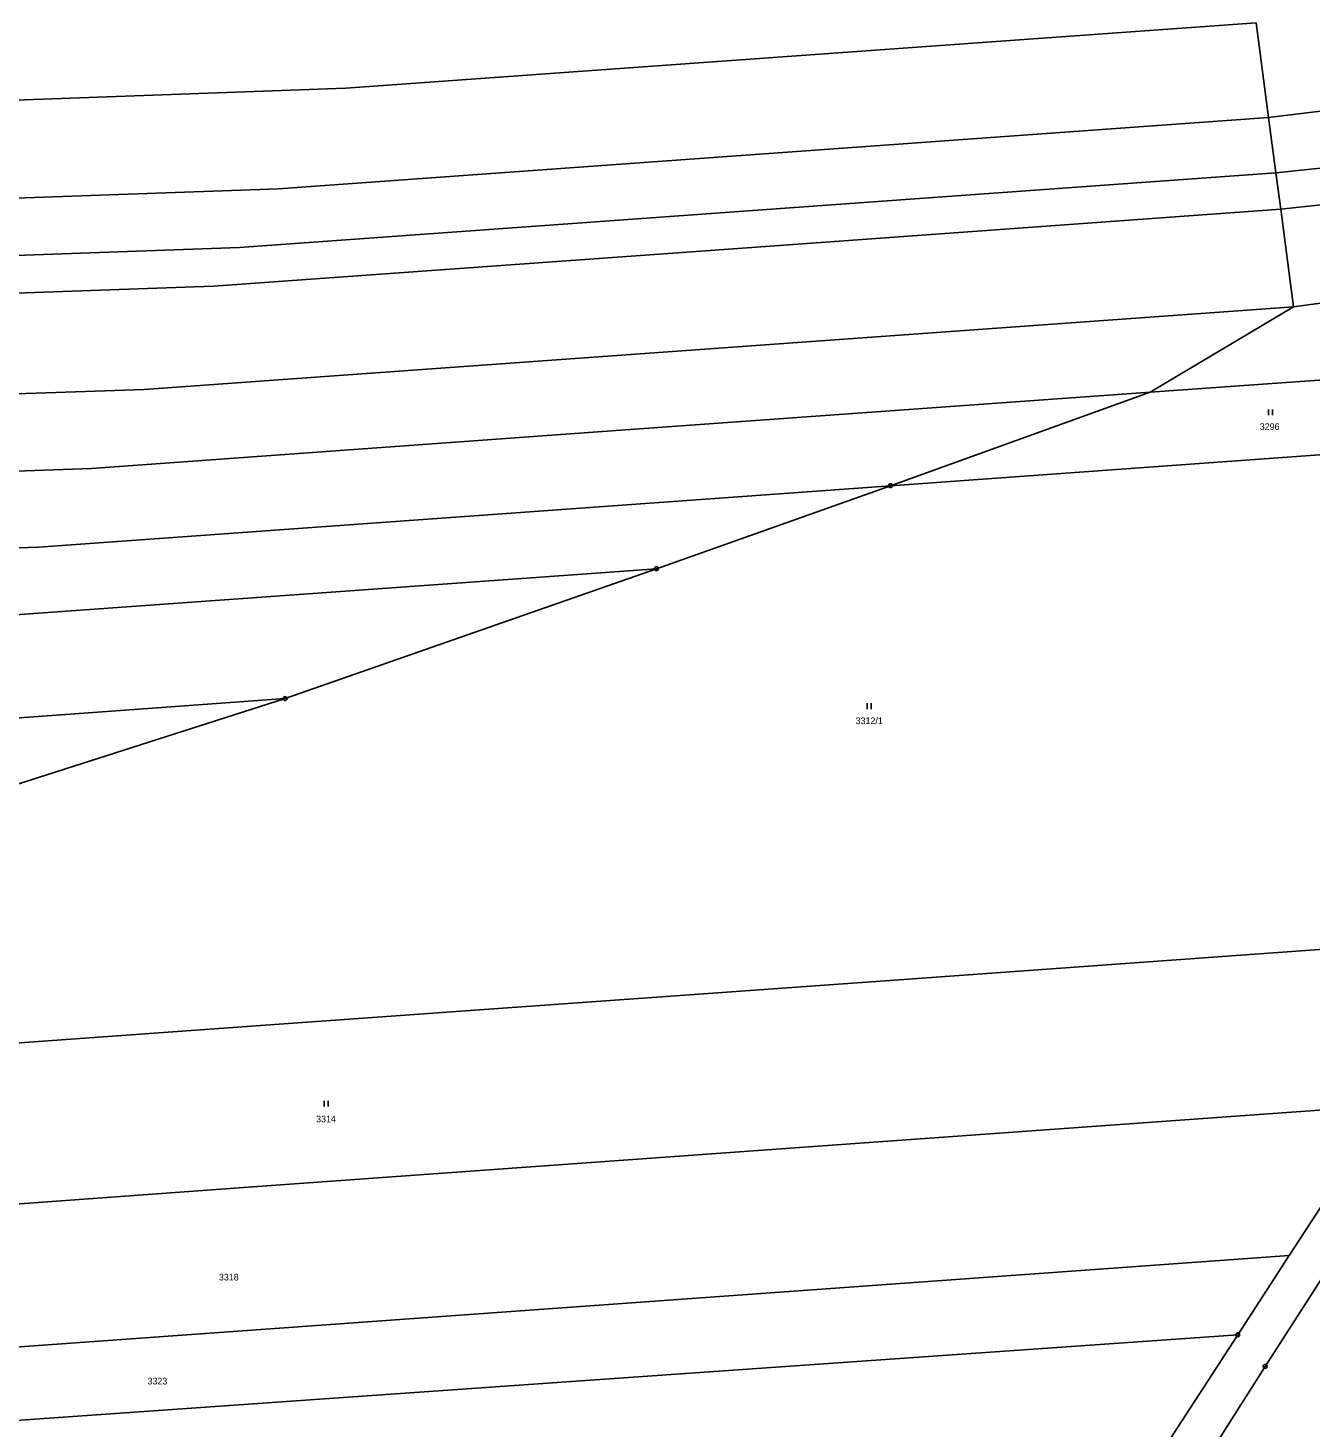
# Model space of a CAD drawing. Extents: x -618848 to -615803, y -1044450 to -1042254.
# Drawn here: x -617311.9 to -616984, y -1043703.1 to -1043345.1 of the extents above; entities that cross this region are included whole.
import ezdxf
from ezdxf.enums import TextEntityAlignment as Align

# ---------------------------------------------------------------- set-up
doc = ezdxf.new("R2010")
doc.units = 0
doc.header["$LTSCALE"] = 0.68
for name, color, linetype, lineweight in [('1', 7, 'Continuous', 25), ('3', 7, 'Continuous', 25), ('8', 7, 'Continuous', 25)]:
    doc.layers.add(name, color=color, linetype=linetype, lineweight=lineweight)
doc.layers.add('2', color=7, linetype='Continuous')

msp = doc.modelspace()

# ---------------------------------------------------------------- linework, layer by layer
at = {"layer": '1'}
for p, q in [((-617114.36, -1043352.18), (-616998.06, -1043343.8)), ((-616998.06, -1043343.8), (-616994.86, -1043368.03)), ((-617230.67, -1043360.55), (-617114.36, -1043352.18)), ((-617360.78, -1043365.17), (-617230.67, -1043360.55)), ((-616994.86, -1043368.03), (-616925.06, -1043359.49)), ((-616994.86, -1043368.03), (-617121.36, -1043377.14)), ((-616994.86, -1043368.03), (-616993, -1043382.17)), ((-616993, -1043382.17), (-616927.39, -1043375.26)), ((-617121.36, -1043377.14), (-617247.87, -1043386.25)), ((-617125.46, -1043391.7), (-616993, -1043382.17)), ((-616993, -1043382.17), (-616991.77, -1043391.49)), ((-617247.87, -1043386.25), (-617368.94, -1043390.54)), ((-616991.77, -1043391.49), (-616929.96, -1043384.84)), ((-617257.91, -1043401.24), (-617125.46, -1043391.7)), ((-616991.77, -1043391.49), (-617128.15, -1043401.31)), ((-616991.77, -1043391.49), (-616988.49, -1043416.39)), ((-617387.08, -1043405.83), (-617257.91, -1043401.24)), ((-617128.15, -1043401.31), (-617264.53, -1043411.13)), ((-617264.53, -1043411.13), (-617385.26, -1043415.42)), ((-617135.35, -1043426.96), (-616988.49, -1043416.39)), ((-616988.49, -1043416.39), (-617025.1, -1043438.25)), ((-617282.21, -1043437.54), (-617135.35, -1043426.96)), ((-617025.1, -1043438.25), (-616949.47, -1043432.81)), ((-617478.58, -1043444.51), (-617282.21, -1043437.54)), ((-617025.1, -1043438.25), (-617160.42, -1043447.99)), ((-617091.46, -1043462.15), (-617025.1, -1043438.25)), ((-617160.42, -1043447.99), (-617295.73, -1043457.73)), ((-616954.25, -1043452.27), (-617091.46, -1043462.15)), ((-617295.73, -1043457.73), (-617457.63, -1043463.48)), ((-617200.32, -1043469.99), (-617091.46, -1043462.15)), ((-617091.46, -1043462.15), (-617151.29, -1043483.37)), ((-617309.18, -1043477.83), (-617200.32, -1043469.99)), ((-617436.78, -1043482.36), (-617309.18, -1043477.83)), ((-617151.29, -1043483.37), (-617321.13, -1043495.59)), ((-617246.21, -1043516.59), (-617151.29, -1043483.37)), ((-617342.3, -1043547.34), (-617246.21, -1043516.59)), ((-617339.64, -1043523.32), (-617246.21, -1043516.59)), ((-616933.16, -1043577.2), (-617090.47, -1043588.53)), ((-617090.47, -1043588.53), (-617247.77, -1043599.85)), ((-617247.77, -1043599.85), (-617405.08, -1043611.18)), ((-617109.97, -1043631.03), (-616964.31, -1043620.54)), ((-616967.81, -1043625.46), (-616989.58, -1043658.99)), ((-617255.63, -1043641.52), (-617109.97, -1043631.03)), ((-616995.75, -1043687.3), (-616959.75, -1043631.31)), ((-617401.29, -1043652.01), (-617255.63, -1043641.52)), ((-616989.58, -1043658.99), (-617164.72, -1043671.6)), ((-617002.72, -1043679.23), (-616989.58, -1043658.99)), ((-617164.72, -1043671.6), (-617339.86, -1043684.2)), ((-617170.62, -1043691.02), (-617002.72, -1043679.23)), ((-617002.72, -1043679.23), (-617022.48, -1043709.69)), ((-617009.18, -1043708.56), (-616995.75, -1043687.3)), ((-617338.51, -1043702.82), (-617170.62, -1043691.02))]:
    msp.add_line(p, q, dxfattribs=at)
msp.add_lwpolyline([(-616988.49, -1043416.39), (-616944, -1043410.38), (-616936.52, -1043409.37)], dxfattribs=at)
at = {"layer": '3'}
for p, q in [((-616994.841, -1043444.15), (-616994.841, -1043442.65)), ((-616993.84, -1043444.15), (-616993.84, -1043442.65)), ((-617097.471, -1043519.29), (-617097.471, -1043517.79)), ((-617096.47, -1043519.29), (-617096.47, -1043517.79)), ((-617236.231, -1043620.91), (-617236.231, -1043619.41)), ((-617235.23, -1043620.91), (-617235.23, -1043619.41))]:
    msp.add_line(p, q, dxfattribs=at)
at = {"layer": '8'}
for centre, radius in [((-617091.46, -1043462.1499), 0.5), ((-617091.46, -1043462.1499), 0.0303), ((-617151.29, -1043483.3699), 0.5), ((-617151.29, -1043483.3699), 0.0303), ((-617246.21, -1043516.5899), 0.5), ((-617246.21, -1043516.5899), 0.0303), ((-617002.72, -1043679.2299), 0.5), ((-617002.72, -1043679.2299), 0.0303), ((-616995.75, -1043687.2999), 0.5), ((-616995.75, -1043687.2999), 0.0303)]:
    msp.add_circle(centre, radius, dxfattribs=at)

# ---------------------------------------------------------------- texts
at = {"layer": '2'}
for s, p in [('3296', (-616997.12, -1043447.905)), ('3314', (-617238.28, -1043624.905)), ('3318', (-617263.14, -1043665.345)), ('3323', (-617281.37, -1043691.935))]:
    msp.add_text(s, height=1.7, dxfattribs=at).set_placement(p)
msp.add_text('3312/1', height=1.7, dxfattribs=at).set_placement((-617096.93, -1043523.115), align=Align.CENTER)

doc.saveas('drawing.dxf')
